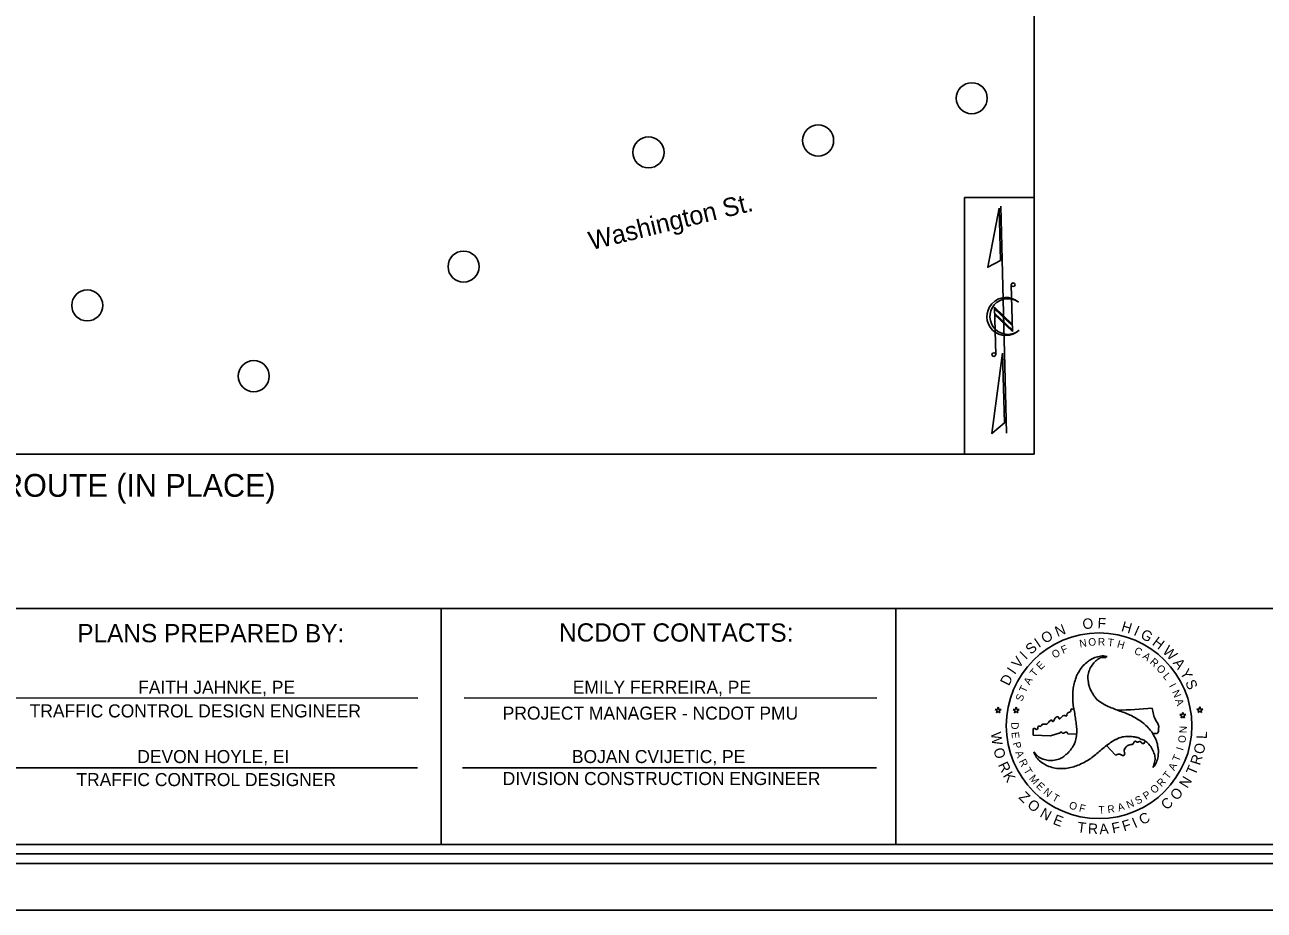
# Model space of a CAD drawing. Extents: x 2141134 to 2191774, y 803576 to 836576.
# Drawn here: x 2154714 to 2174677, y 803576 to 817833 of the extents above; entities that cross this region are included whole.
import ezdxf

# ---------------------------------------------------------------- set-up
doc = ezdxf.new("R2010")
doc.units = 0
for name, color, linetype in [('Exist Cultural Recreational Athletic Track', 7, 'Continuous'), ('Exist Road Primary NC Mileage Hundredths English Label', 7, 'Continuous'), ('Exist Road Primary US Service Mileage Hundredths English Label', 7, 'Continuous'), ('Exist Road Primary US Shield CELL', 7, 'Continuous'), ('Exist Road Secondary Type 20 SR Number Label', 7, 'Continuous'), ('Level 51', 7, 'Continuous'), ('Level 52', 7, 'Continuous'), ('Level 53', 7, 'Continuous')]:
    doc.layers.add(name, color=color, linetype=linetype)

msp = doc.modelspace()

# ---------------------------------------------------------------- linework, layer by layer
at = {"layer": 'Exist Cultural Recreational Athletic Track'}
for q in [(2170969, 815051), (2169850, 810917)]:
    msp.add_line((2170969, 810917), q, dxfattribs=at)
msp.add_lwpolyline([(2151443, 822603), (2170969, 822603), (2170969, 815051), (2169850, 815051), (2169850, 810917), (2151443, 810917)], close=True, dxfattribs=at)
at = {"layer": 'Exist Road Primary NC Mileage Hundredths English Label'}
for p, q in [((2170525, 811260), (2170434, 814915)), ((2170603, 813647), (2170622, 812897)), ((2170619, 813014), (2170333, 813286)), ((2170333, 813286), (2170352, 812524)), ((2170714, 813370), (2170718, 813367)), ((2170620, 812986), (2170333, 813259)), ((2170333, 813259), (2170335, 813190)), ((2170621, 812917), (2170335, 813190)), ((2170335, 813190), (2170621, 812917)), ((2170622, 812897), (2170335, 813169)), ((2170621, 812917), (2170620, 812986))]:
    msp.add_line(p, q, dxfattribs=at)
for points in [[(2170409, 814883), (2170224, 813928), (2170430, 814039)], [(2170463, 812547), (2170288, 811254), (2170491, 811423)]]:
    msp.add_lwpolyline(points, close=True, dxfattribs=at)
for centre in [(2170633, 813647), (2170322, 812522)]:
    msp.add_circle(centre, 29.8, dxfattribs=at)
for centre, radius, start, end in [((2170517, 813135), 307, 49.2729, 313.8269), ((2170547, 813135), 288, 54.5279, 310.0616)]:
    msp.add_arc(centre, radius, start, end, dxfattribs=at)
at = {"layer": 'Exist Road Primary US Service Mileage Hundredths English Label'}
for p, q in [((2170525, 811260), (2170434, 814915)), ((2170603, 813647), (2170622, 812897)), ((2170619, 813014), (2170333, 813286)), ((2170333, 813286), (2170352, 812524)), ((2170714, 813370), (2170718, 813367)), ((2170620, 812986), (2170333, 813259)), ((2170333, 813259), (2170335, 813190)), ((2170621, 812917), (2170335, 813190)), ((2170335, 813190), (2170621, 812917)), ((2170622, 812897), (2170335, 813169)), ((2170621, 812917), (2170620, 812986))]:
    msp.add_line(p, q, dxfattribs=at)
for points in [[(2170409, 814883), (2170224, 813928), (2170430, 814039)], [(2170463, 812547), (2170288, 811254), (2170491, 811423)]]:
    msp.add_lwpolyline(points, close=True, dxfattribs=at)
for centre in [(2170633, 813647), (2170322, 812522)]:
    msp.add_circle(centre, 29.8, dxfattribs=at)
for centre, radius, start, end in [((2170517, 813135), 307, 49.2729, 313.8269), ((2170547, 813135), 288, 54.5279, 310.0616)]:
    msp.add_arc(centre, radius, start, end, dxfattribs=at)
at = {"layer": 'Exist Road Secondary Type 20 SR Number Label'}
for p, q in [((2146644, 808435), (2175119, 808435)), ((2168744, 808437), (2168741, 804633)), ((2170345, 806810), (2170374, 806789)), ((2170381, 806810), (2170345, 806810)), ((2170374, 806789), (2170363, 806754)), ((2170363, 806754), (2170391, 806775)), ((2170391, 806843), (2170381, 806810)), ((2170403, 806810), (2170391, 806843)), ((2170391, 806775), (2170421, 806754)), ((2170391, 806775), (2170421, 806754)), ((2170439, 806810), (2170403, 806810)), ((2170410, 806789), (2170439, 806810)), ((2170410, 806789), (2170439, 806810)), ((2170421, 806754), (2170410, 806789)), ((2170421, 806754), (2170410, 806789)), ((2170669, 806810), (2170633, 806810)), ((2170633, 806810), (2170662, 806788)), ((2170662, 806788), (2170652, 806754)), ((2170652, 806754), (2170680, 806775)), ((2170680, 806843), (2170669, 806810)), ((2170692, 806810), (2170680, 806843)), ((2170680, 806775), (2170709, 806754)), ((2170728, 806810), (2170692, 806810)), ((2170698, 806788), (2170728, 806810)), ((2170709, 806754), (2170698, 806788)), ((2173354, 806727), (2173318, 806727)), ((2173318, 806727), (2173347, 806706)), ((2173347, 806706), (2173337, 806671)), ((2173337, 806671), (2173365, 806692)), ((2173365, 806760), (2173354, 806727)), ((2173377, 806727), (2173365, 806760)), ((2173365, 806692), (2173394, 806671)), ((2173413, 806727), (2173377, 806727)), ((2173383, 806706), (2173413, 806727)), ((2173394, 806671), (2173383, 806706)), ((2173629, 806815), (2173593, 806815)), ((2173593, 806815), (2173622, 806793)), ((2173622, 806793), (2173612, 806759)), ((2173612, 806759), (2173640, 806780)), ((2173640, 806848), (2173629, 806815)), ((2173652, 806815), (2173640, 806848)), ((2173640, 806780), (2173669, 806759)), ((2173688, 806815), (2173652, 806815)), ((2173659, 806793), (2173688, 806815)), ((2173669, 806759), (2173659, 806793)), ((2170954, 806396), (2170957, 806485)), ((2171233, 806386), (2170954, 806396)), ((2171392, 806433), (2171233, 806386)), ((2171515, 806414), (2171656, 806413)), ((2172139, 806228), (2172282, 806072)), ((2146478, 804485), (2175270, 804485)), ((2175119, 804632), (2146644, 804632)), ((2146333, 804326), (2190716, 804326))]:
    msp.add_line(p, q, dxfattribs=at)
msp.add_circle((2172016, 806546), 1495, dxfattribs=at)
for start, end in [(265.6785, 265.9762), (271.2035, 275.3236)]:
    msp.add_arc((2172152, 814547), 7752, start, end, dxfattribs=at)
for points in [[(2170967, 806127), (2171025, 806060), (2171098, 806013), (2171181, 805992), (2171274, 805987), (2171370, 806009), (2171433, 806041), (2171460, 806063), (2171506, 806099), (2171539, 806135), (2171595, 806213), (2171638, 806306), (2171655, 806412), (2171656, 806421), (2171655, 806521), (2171642, 806622), (2171628, 806719), (2171610, 806820), (2171594, 806920), (2171592, 807017), (2171598, 807129), (2171614, 807224), (2171646, 807323), (2171663, 807369), (2171686, 807406), (2171744, 807495), (2171820, 807566), (2171870, 807604), (2171917, 807629), (2171925, 807633), (2172019, 807663), (2172112, 807667), (2172144, 807659)], [(2172146, 807662), (2172144, 807659), (2172058, 807643), (2171980, 807603), (2171920, 807542), (2171870, 807464), (2171841, 807370), (2171837, 807299), (2171843, 807265), (2171851, 807207), (2171864, 807160), (2171906, 807074), (2171964, 806990), (2172048, 806921), (2172055, 806916), (2172141, 806867), (2172236, 806827), (2172327, 806792), (2172423, 806757), (2172517, 806719), (2172603, 806673), (2172697, 806612), (2172771, 806551), (2172841, 806475), (2172873, 806436), (2172893, 806397), (2172941, 806303), (2172965, 806202), (2172973, 806139), (2172971, 806086), (2172971, 806077), (2172948, 805980), (2172905, 805897), (2172883, 805875)], [(2170957, 806485), (2170954, 806493), (2170969, 806503), (2171010, 806486), (2171031, 806504), (2171030, 806521), (2171047, 806539), (2171075, 806534), (2171100, 806566), (2171124, 806572), (2171174, 806572), (2171233, 806631), (2171257, 806635), (2171264, 806619), (2171279, 806616), (2171305, 806665), (2171312, 806672), (2171357, 806690), (2171369, 806681), (2171373, 806659), (2171379, 806656), (2171394, 806666), (2171415, 806692), (2171452, 806712), (2171496, 806706), (2171503, 806742), (2171554, 806776), (2171564, 806797), (2171567, 806817)], [(2172881, 806422), (2172963, 806432), (2172975, 806497), (2172976, 806551), (2172942, 806614), (2172892, 806730), (2172871, 806829)], [(2172883, 805875), (2172912, 805957), (2172916, 806044), (2172893, 806127), (2172851, 806210), (2172784, 806281), (2172725, 806320), (2172692, 806332), (2172639, 806355), (2172590, 806366), (2172495, 806374), (2172393, 806365), (2172292, 806327), (2172284, 806323), (2172198, 806272), (2172117, 806211), (2172039, 806150), (2171962, 806084), (2171882, 806020), (2171799, 805970), (2171699, 805919), (2171609, 805886), (2171509, 805864), (2171459, 805855), (2171415, 805856), (2171311, 805862), (2171210, 805892), (2171153, 805916), (2171108, 805946), (2171100, 805950), (2171026, 806017), (2170977, 806096), (2170967, 806127)], [(2171515, 806414), (2171504, 806436), (2171482, 806442), (2171451, 806427), (2171428, 806427), (2171403, 806446), (2171392, 806433)], [(2172282, 806072), (2172338, 806089), (2172385, 806071), (2172408, 806068), (2172427, 806082), (2172421, 806152), (2172437, 806185), (2172513, 806241), (2172560, 806252), (2172595, 806295), (2172609, 806294), (2172630, 806282), (2172678, 806291), (2172717, 806260), (2172739, 806262), (2172757, 806297)]]:
    msp.add_spline(points, degree=3, dxfattribs=at)
at = {"layer": 'Level 51'}
for p, q in [((2161422, 808436), (2161419, 804632)), ((2154389, 806993), (2161045, 806992)), ((2161793, 806993), (2168437, 806992)), ((2154373, 805869), (2161041, 805869)), ((2161762, 805869), (2168431, 805868))]:
    msp.add_line(p, q, dxfattribs=at)
at = {"layer": 'Level 52'}
for centre in [(2169966, 816651), (2167492, 815970), (2164760, 815779), (2161781, 813939), (2155720, 813315), (2158402, 812175)]:
    msp.add_circle(centre, 250, dxfattribs=at)
at = {"layer": 'Level 53'}
msp.add_lwpolyline([(2141134, 803576), (2191774, 803576), (2191774, 836576), (2141134, 836576)], close=True, dxfattribs=at)

# ---------------------------------------------------------------- texts
at = {"layer": 'Exist Cultural Recreational Athletic Track'}
for s, p in [('TRAFFIC CONTROL DESIGN ENGINEER', (2154793, 806680)), ('PROJECT MANAGER - NCDOT PMU', (2162412, 806644)), ('TRAFFIC CONTROL DESIGNER', (2155546, 805574)), ('DIVISION CONSTRUCTION ENGINEER', (2162412, 805591))]:
    msp.add_text(s, height=210, dxfattribs=at).set_placement(p)
at = {"layer": 'Exist Road Primary US Shield CELL'}
msp.add_text('DETOUR ROUTE (IN PLACE)', height=367.22, dxfattribs=at).set_placement((2152123, 810233))
at = {"layer": 'Exist Road Secondary Type 20 SR Number Label'}
for s, height, rotation, p in [('O', 167, 5.7649, (2171758, 808099)), ('F', 167, 357.2575, (2171989, 808118)), ('N', 167, 21.5861, (2171346, 807975)), ('H', 167, 343.454, (2172363, 808074)), ('I', 167, 335.804, (2172562, 808012)), ('G', 167, 331.5167, (2172670, 807966)), ('S', 167, 40.5848, (2170919, 807685)), ('I', 167, 34.3808, (2171047, 807795)), ('O', 167, 30.0935, (2171143, 807863)), ('N', 121, 9.0227, (2171709, 807807)), ('O', 121, 3.9446, (2171847, 807831)), ('R', 121, 358.8665, (2171996, 807840)), ('T', 121, 353.7884, (2172150, 807832)), ('H', 121, 343.6322, (2172297, 807811)), ('H', 167, 323.4632, (2172861, 807858)), ('V', 167, 51.5806, (2170723, 807458)), ('I', 167, 44.8722, (2170837, 807601)), ('O', 121, 29.335, (2171296, 807625)), ('F', 121, 24.2569, (2171436, 807703)), ('C', 121, 333.4761, (2172571, 807714)), ('A', 121, 323.3199, (2172707, 807644)), ('W', 167, 315.8133, (2173027, 807732)), ('I', 167, 55.8679, (2170659, 807361)), ('T', 121, 49.6473, (2170981, 807326)), ('E', 121, 44.5692, (2171076, 807436)), ('R', 121, 318.2418, (2172824, 807559)), ('O', 121, 313.1637, (2172930, 807462)), ('A', 167, 306.7762, (2173199, 807556)), ('Y', 167, 299.7484, (2173313, 807401)), ('D', 167, 63.459, (2170564, 807177)), ('A', 121, 59.8035, (2170896, 807194)), ('L', 121, 308.0856, (2173037, 807340)), ('S', 167, 293.2249, (2173400, 807246)), ('T', 121, 64.8816, (2170832, 807068)), ('I', 121, 297.9295, (2173138, 807190)), ('N', 121, 292.8514, (2173189, 807093)), ('S', 121, 69.9597, (2170779, 806930)), ('A', 121, 287.7733, (2173242, 806959)), ('D', 121, 270.272, (2170601, 806602)), ('N', 121, 87.733, (2173427, 806424)), ('W', 167, 278.15, (2170271, 806433)), ('E', 121, 275.3501, (2170605, 806441)), ('P', 121, 285.5063, (2170625, 806268)), ('O', 121, 82.9269, (2173406, 806262)), ('L', 167, 87.429, (2173751, 806331)), ('O', 167, 287.1147, (2170310, 806163)), ('A', 121, 290.5843, (2170665, 806119)), ('T', 121, 67.6926, (2173303, 805958)), ('I', 121, 72.7707, (2173370, 806137)), ('R', 167, 72.7519, (2173640, 805899)), ('O', 167, 78.9896, (2173701, 806079)), ('R', 167, 295.5541, (2170384, 805917)), ('R', 121, 295.6624, (2170721, 805975)), ('T', 121, 300.7405, (2170796, 805829)), ('A', 121, 62.6145, (2173229, 805814)), ('T', 167, 66.881, (2173565, 805736)), ('K', 167, 301.7918, (2170462, 805743)), ('M', 121, 310.8967, (2170883, 805693)), ('R', 121, 47.3803, (2173023, 805552)), ('T', 121, 52.4584, (2173131, 805676)), ('N', 167, 58.892, (2173438, 805528)), ('Z', 167, 316.1688, (2170710, 805383)), ('E', 121, 315.9748, (2170994, 805566)), ('N', 121, 321.0529, (2171108, 805461)), ('P', 121, 32.146, (2172770, 805349)), ('O', 121, 42.3022, (2172906, 805443)), ('O', 167, 50.4526, (2173273, 805331)), ('O', 167, 322.5233, (2170847, 805245)), ('T', 121, 331.209, (2171249, 805353)), ('O', 121, 341.3652, (2171522, 805219)), ('F', 121, 346.4433, (2171686, 805170)), ('A', 121, 16.9118, (2172334, 805164)), ('N', 121, 21.9899, (2172486, 805210)), ('S', 121, 27.068, (2172633, 805273)), ('C', 167, 43.0807, (2173107, 805179)), ('N', 167, 330.9626, (2171050, 805088)), ('E', 167, 338.9517, (2171262, 804968)), ('T', 121, 1.6775, (2172010, 805131)), ('R', 121, 6.7556, (2172159, 805138)), ('C', 167, 28.0033, (2172714, 804943)), ('T', 167, 352.6948, (2171659, 804834)), ('R', 167, 358.5656, (2171836, 804807)), ('A', 167, 4.8034, (2172026, 804797)), ('F', 167, 11.7751, (2172238, 804811)), ('F', 167, 17.7627, (2172418, 804844)), ('I', 167, 23.7503, (2172593, 804895))]:
    msp.add_text(s, height=height, rotation=rotation, dxfattribs=at).set_placement(p)
for s, p in [('FAITH JAHNKE, PE', (2156540, 807061)), ('EMILY FERREIRA, PE', (2163540, 807061)), ('DEVON HOYLE, EI', (2156526, 805945)), ('BOJAN CVIJETIC, PE', (2163526, 805945))]:
    msp.add_text(s, height=210, dxfattribs=at).set_placement(p)
at = {"layer": 'Level 51'}
for s, p in [('PLANS PREPARED BY:', (2155559, 807891)), ('NCDOT CONTACTS:', (2163319, 807902))]:
    msp.add_text(s, height=293.71, rotation=359.9598, dxfattribs=at).set_placement(p)
at = {"layer": 'Level 52'}
msp.add_text('Washington St.', height=298.13, rotation=13.6442, dxfattribs=at).set_placement((2163837, 814204))

doc.saveas('drawing.dxf')
